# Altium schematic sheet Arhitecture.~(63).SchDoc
size A3; SheetNumber: 1; SheetTotal: 5
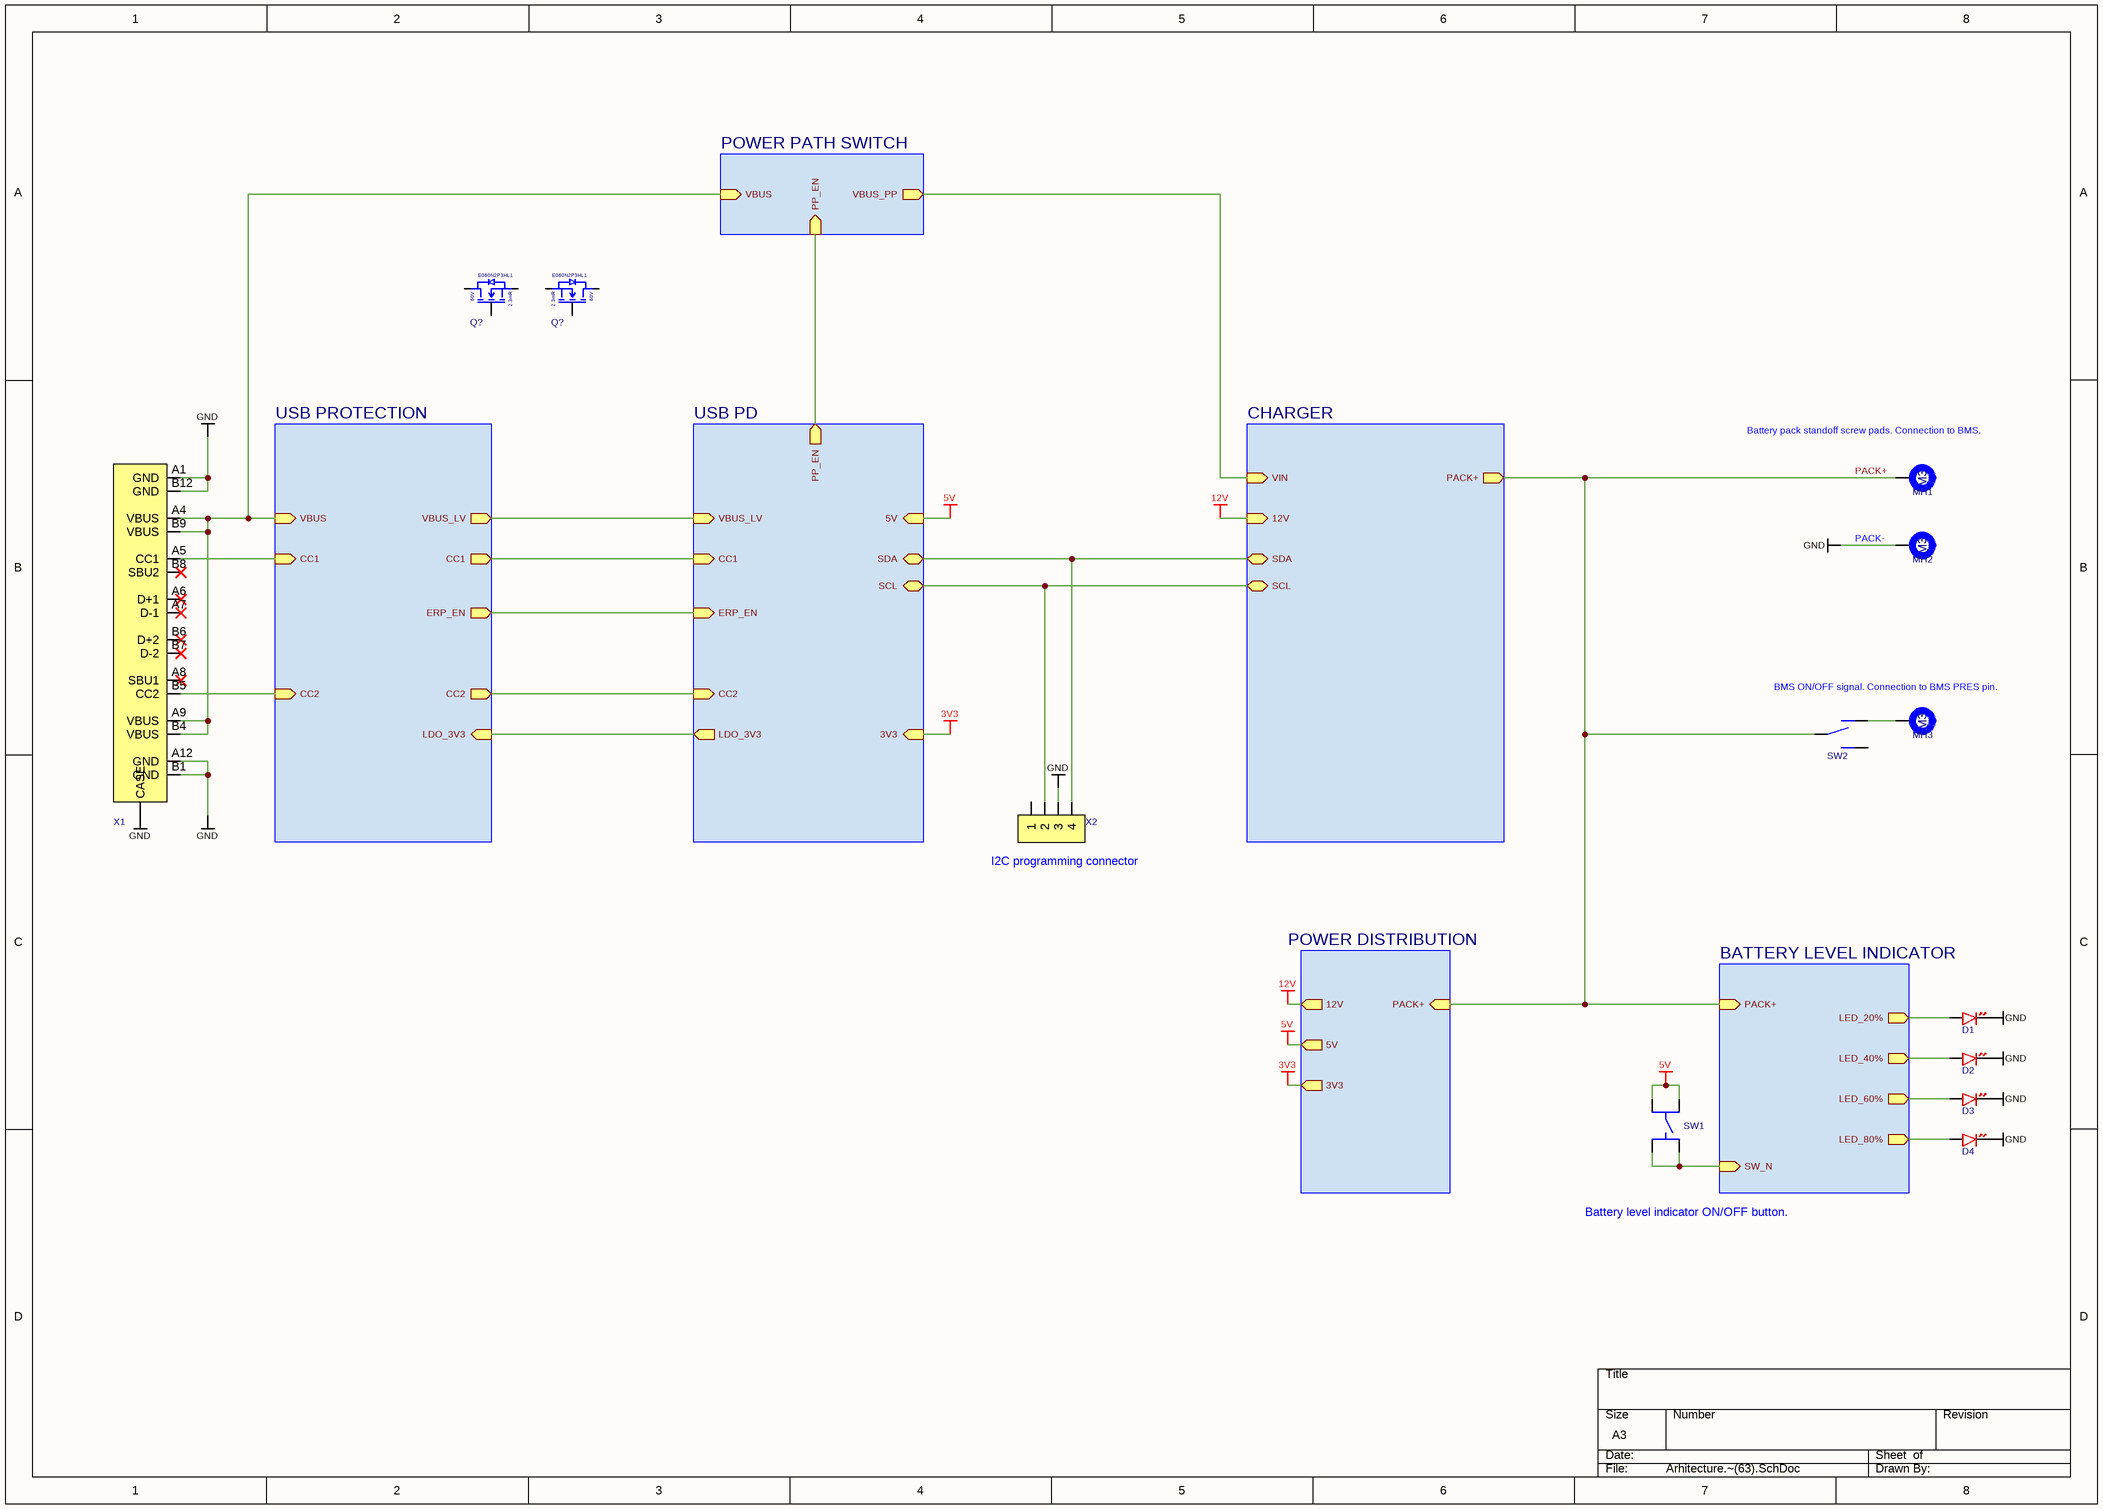
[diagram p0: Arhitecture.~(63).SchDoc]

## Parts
(Parts that share a designator on the sheet are numbered #1, #2 ... from top to bottom, then left to right.)
D1  XL-1608SURC-06  [DIODE_0603]  (value not drawn)
D2  XL-1608SURC-06  [DIODE_0603]  (value not drawn)
D3  XL-1608SURC-06  [DIODE_0603]  (value not drawn)
D4  XL-1608SURC-06  [DIODE_0603]  (value not drawn)
MH1  Hole size: M3  [M3 Plated]  (hidden comment: M?)  (no BOM)
MH2  Hole size: M3  [M3 Plated]  (hidden comment: M?)  (no BOM)
MH3  Hole size: M3  [M3 Plated]  (hidden comment: M?)  (no BOM)
Q?#1  Rds: 2.3mR  Voltage: 60V  [DFN-8 (5x6)]  (hidden comment: E060N2P3HL1)
Q?#2  Rds: 2.3mR  Voltage: 60V  [DFN-8 (5x6)]  (hidden comment: E060N2P3HL1)
SW1  TS4560TP  [TS4560TP]  (value not drawn)
SW2  SS-3235S-L3  [SS-3235S-L3]  (value not drawn)
X1  TYPE-C 16P LTH6.8  [TYPE-C 16P LTH6.8]  (value not drawn)
X2  B4B-PH-K-S(LF)(SN)  [B4B-PH-K-S(LF)(SN)]  (value not drawn)

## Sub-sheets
BATTERY LEVEL INDICATOR = Battery level indicator.SchDoc: PACK+ (in), SW_N (in), LED_20% (out), LED_40% (out), LED_60% (out), LED_80% (out)
CHARGER = Charger.SchDoc: PACK+ (out), VIN (in), SDA (bidir), SCL (bidir), 12V (in)
POWER DISTRIBUTION = Power distribution.SchDoc: PACK+ (in), 12V (out), 5V (out), 3V3 (out)
POWER PATH SWITCH = Power path switch.SchDoc: VBUS (in), VBUS_PP (out), PP_EN (in)
USB PD = USB PD.SchDoc: VBUS_LV (in), ERP_EN (in), CC1 (in), LDO_3V3 (out), SDA (bidir), SCL (bidir), 5V (in), 3V3 (in), CC2 (in), PP_EN (out)
USB PROTECTION = USB protection.SchDoc: VBUS (in), CC1 (in), CC2 (in), VBUS_LV (out), ERP_EN (out), CC1 (out), LDO_3V3 (in), CC2 (out)

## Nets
3V3: sheet POWER DISTRIBUTION/3V3, sheet USB PD/3V3
5V: SW1.1 SW1.2 ; sheet POWER DISTRIBUTION/5V, sheet USB PD/5V
12V: sheet CHARGER/12V, sheet POWER DISTRIBUTION/12V
GND: D1.K D2.K D3.K D4.K MH2.1 X1.A1(GND) X1.A12(GND) X1.B1(GND) X1.B12(GND) X1.CASE X2.3
PACK+: MH1.1 SW2.2 ; sheet CHARGER/PACK+, sheet POWER DISTRIBUTION/PACK+, sheet BATTERY LEVEL INDICATOR/PACK+
NetD1_A: D1.A ; sheet BATTERY LEVEL INDICATOR/LED_20%
NetD2_A: D2.A ; sheet BATTERY LEVEL INDICATOR/LED_40%
NetD3_A: D3.A ; sheet BATTERY LEVEL INDICATOR/LED_60%
NetD4_A: D4.A ; sheet BATTERY LEVEL INDICATOR/LED_80%
NetMH3_1: MH3.1 SW2.1
NetSW1_3: SW1.3 SW1.4 ; sheet BATTERY LEVEL INDICATOR/SW_N
NetX1_A4: X1.A4(VBUS) X1.A9(VBUS) X1.B4(VBUS) X1.B9(VBUS) ; sheet USB PROTECTION/VBUS, sheet POWER PATH SWITCH/VBUS
NetX1_A5: X1.A5(CC1) ; sheet USB PROTECTION/CC1
NetX1_B5: X1.B5(CC2) ; sheet USB PROTECTION/CC2
NetX2_2: X2.2 ; sheet CHARGER/SCL, sheet USB PD/SCL
NetX2_4: X2.4 ; sheet CHARGER/SDA, sheet USB PD/SDA
(unnamed): sheet CHARGER/VIN, sheet POWER PATH SWITCH/VBUS_PP
(unnamed): sheet USB PD/VBUS_LV, sheet USB PROTECTION/VBUS_LV  [a separate net that carries the same name]
(unnamed): sheet USB PD/ERP_EN, sheet USB PROTECTION/ERP_EN  [a separate net that carries the same name]
(unnamed): sheet USB PD/CC1, sheet USB PROTECTION/CC1  [a separate net that carries the same name]
(unnamed): sheet USB PD/LDO_3V3, sheet USB PROTECTION/LDO_3V3  [a separate net that carries the same name]
(unnamed): sheet USB PD/CC2, sheet USB PROTECTION/CC2  [a separate net that carries the same name]
(unnamed): sheet USB PD/PP_EN, sheet POWER PATH SWITCH/PP_EN  [a separate net that carries the same name]

Not connected (* = marked no-connect by the designer): Q?#1 D G S; Q?#2 D G S; SW2 3; X1 A6(D+1)* A7(D-1)* A8(SBU1)* B6(D+2)* B7(D-2)* B8(SBU2)*; X2 1

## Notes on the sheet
- (near MH1) Battery pack standoff screw pads. Connection to BMS.
- (near MH2) PACK-
- BMS ON/OFF signal. Connection to BMS PRES pin.
- (near X2) I2C programming connector
- Battery level indicator ON/OFF button.

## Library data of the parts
D1-D4 = XL-1608SURC-06: LED Red 0603 25mA; Manufacturer: Xinglight
MH1-MH3 = Mounting hole: Generic mounting hole symbol
Q?#1 Q?#2 = E060N2P3HL1: Nmos 60V 180A 2.3mR PDFN5x6-8; Manufacturer: Existar
SW1 = TS4560TP: Switch Tactile SMD 4.5x4.5mm 6mmH SPST; Manufacturer: Shou Han
SW2 = SS-3235S-L3: Switch Slide SMD 9.1x3.5mm 6.6mmH; Manufacturer: XKB Connection
X1 = TYPE-C 16P LTH6.8: USB-C 16P SMD Vertical 6.50mmH; Manufacturer: Shou Han
X2 = B4B-PH-K-S(LF)(SN): Pin header 1x4 2.00mmP THT Vertical JST PH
